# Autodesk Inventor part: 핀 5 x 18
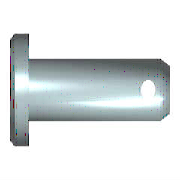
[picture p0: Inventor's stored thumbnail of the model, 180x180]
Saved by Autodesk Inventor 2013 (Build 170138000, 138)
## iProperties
Created: 2012-02
Part Number: 핀 5 x 18
Material: 강철
Description: 머리가 있는 클레비스 핀
Document SubType Name: Modeling
Standard: ISO 2341
Designer: test
Standard Revision: Second edition 1986-11-01
Standards Organization: ISO
Language: ko-KR
Size Designation: B - 5 x 18
Categories: <MemberInstance><Categories><Category DisplayName="조임쇠" InternalName="e4da775c-781d-43d5-af7c-5136215cf5a6" Mnemonic="FSTN"><Category DisplayName="핀" InternalNa
Density: 7.85 g/cm^3
IsCustomPart: 1
Author: test
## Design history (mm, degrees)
sketch "스케치1"
  geometry: L1 (-1.6, 0)-(-1.6, 4); L2 (-1.6, 4)-(0, 4); L3 (0, 4)-(0, 2.5); L4 (0, 2.5)-(18, 2.5); L5 (18, 2.5)-(18, 0); L6 (-1.6, 0)-(18, 0); L7 (-4, 0)-(17, 0) reference; L8 (0, -0.98)-(0, 3.08) reference; C1 r 0.6 at (15.1, 0)
  constraints: 12 end point, 3 parallel, 2 collinear, 2 perpendicular, 1 centre point, 1 point on line, 1 vertical
  dimensions: "d0" = 5 diameter of L4 L6 (= NND); "d1" = 8 diameter of L2 L6 (= KOD); "d2" = 1.6 distance of L1.end L2.end (= KOH); "d3" = 18 distance of L3.end L4.end (= NLG); "d5" = 2.9 distance from line of L5 C1.centre (= DIST); "d6" = 1.2 diameter of C1 (= BOR)
revolve "본체" stored, may be unused: angle "d4" = 90 deg
extrude "구멍" cut sketch "스케치1" stored distance "d7" = 5 (= NND); taper "d8" = 0 deg
workaxis "Work Axis1"
workplane "Work Plane1"
body "Solid1"
chamfer "모따기1" distance "d9" = 1 (= PHH2); stored, may be unused: angle "d10" = 45 deg (= FAWI2), second distance "d16" = 1 (= PHH2)
chamfer "모따기2" distance "d11" = 2 (= PHH1); stored, may be unused: angle "d12" = 30 deg (= FAWI1), second distance "d17" = 2 (= PHH1)
other parameters: "PHH1" = 2 [user parameter; used in 2 equation terms], "PHH2" = 1 [user parameter; used in 2 equation terms], "KOD" = 8 [user parameter; used in 1 equation term], "KOH" = 1.6 [user parameter; used in 1 equation term], "NND" = 5 [user parameter; used in 2 equation terms], "FAWI1" = 30 deg [user parameter; used in 1 equation term], "FAWI2" = 45 deg [user parameter; used in 1 equation term], "DIST" = 2.9 [user parameter; used in 1 equation term], "BOR" = 1.2 [user parameter; used in 1 equation term], "NLG" = 18 [user parameter; used in 1 equation term], "d13" = 0, "d14" = 0, "d27" = 0, "d28" = 0, "d29" = 0, "d30" = 0, "d31" = 0
